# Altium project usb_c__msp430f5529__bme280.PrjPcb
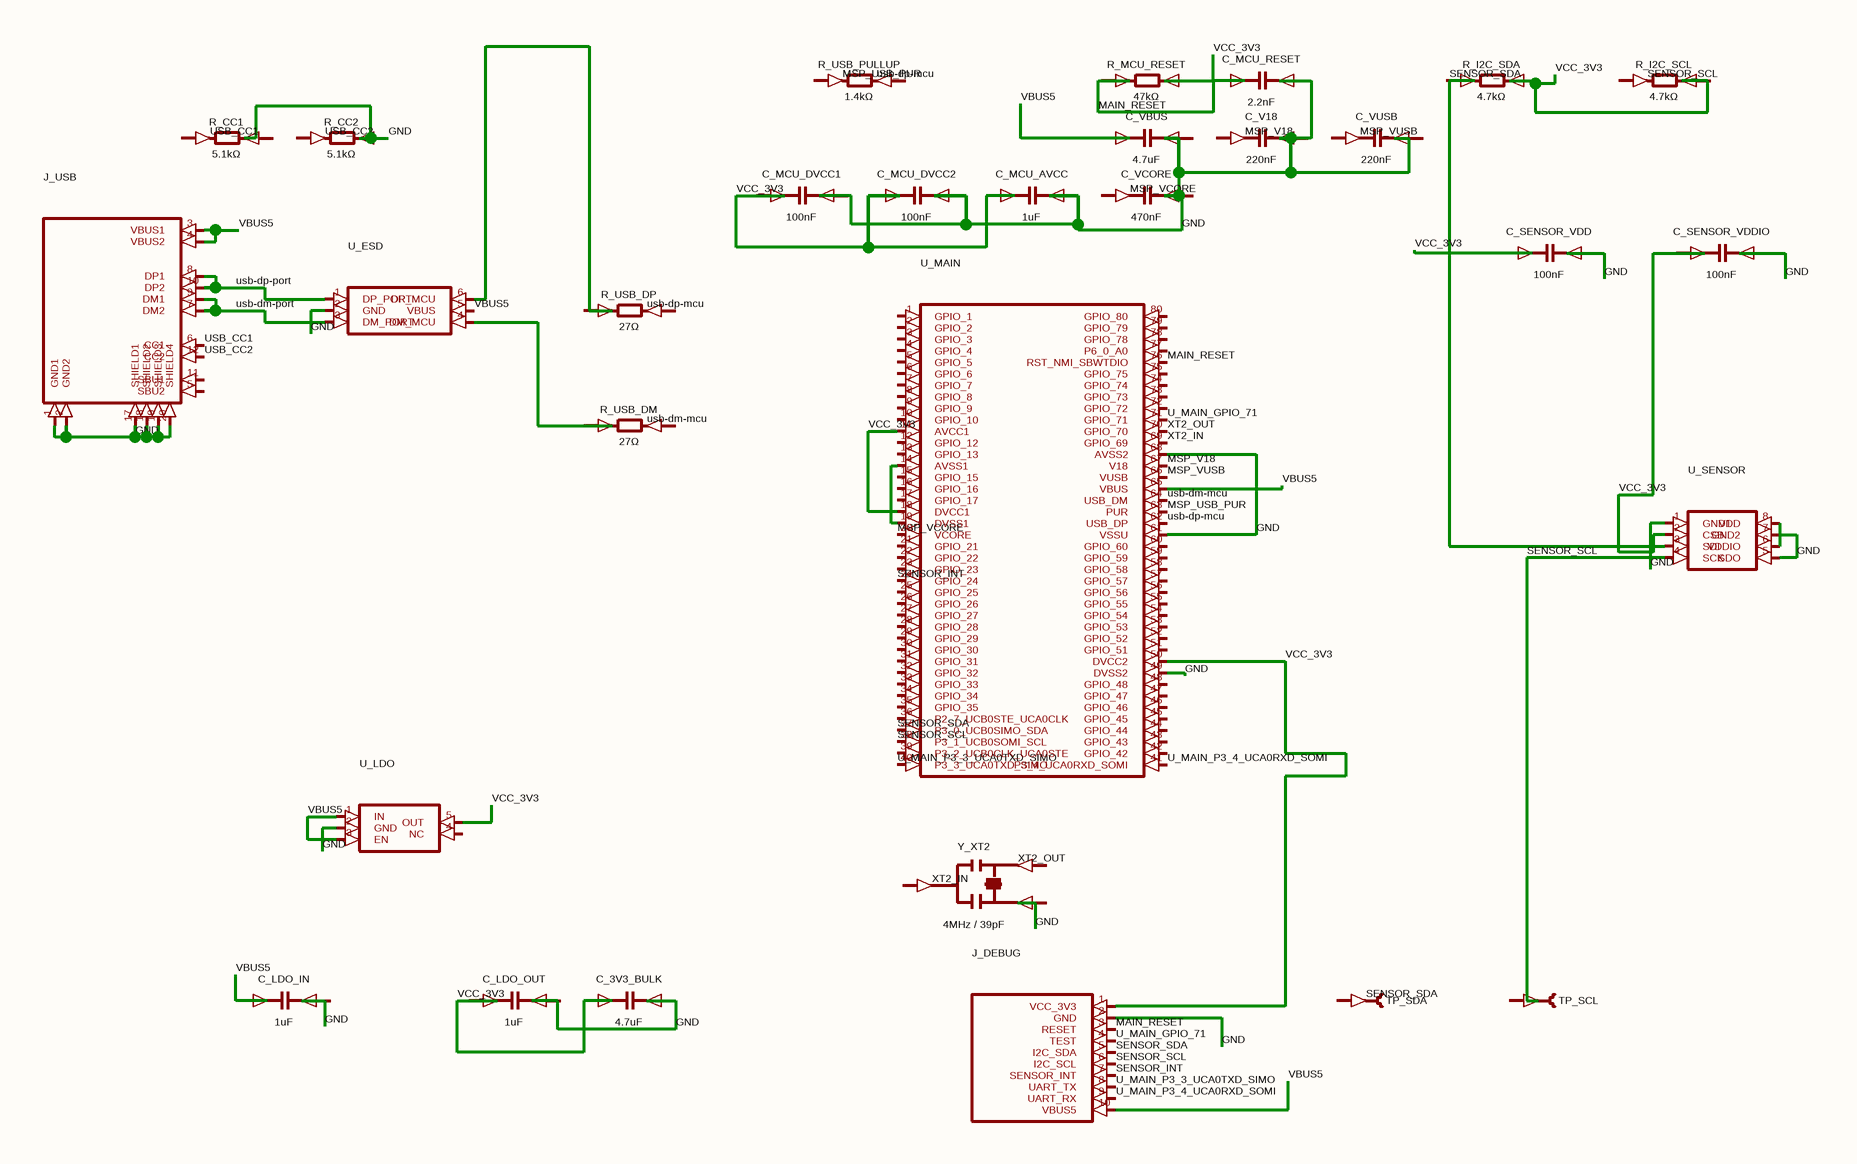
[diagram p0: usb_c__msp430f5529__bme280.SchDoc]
1 sheet, 30 parts. Net scope: global (net labels, ports and power ports of the same name join across sheets).
Board file: usb_c__msp430f5529__bme280.PcbDoc

## Sheet usb_c__msp430f5529__bme280.SchDoc
size 204 x 144 mm

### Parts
C_3V3_BULK  4.7uF
C_LDO_IN  1uF
C_LDO_OUT  1uF
C_MCU_AVCC  1uF
C_MCU_DVCC1  100nF
C_MCU_DVCC2  100nF
C_MCU_RESET  2.2nF
C_SENSOR_VDD  100nF
C_SENSOR_VDDIO  100nF
C_V18  220nF
C_VBUS  4.7uF
C_VCORE  470nF
C_VUSB  220nF
J_DEBUG  (no value)
J_USB  (no value)
R_CC1  5.1kΩ
R_CC2  5.1kΩ
R_I2C_SCL  4.7kΩ
R_I2C_SDA  4.7kΩ
R_MCU_RESET  47kΩ
R_USB_DM  27Ω
R_USB_DP  27Ω
R_USB_PULLUP  1.4kΩ
TP_SCL  (no value)
TP_SDA  (no value)
U_ESD  (no value)
U_LDO  (no value)
U_MAIN  (no value)
U_SENSOR  (no value)
Y_XT2  4MHz / 39pF

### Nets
GND: C_3V3_BULK.2(neg) C_MCU_AVCC.2(neg) C_MCU_DVCC1.2(neg) C_MCU_DVCC2.2(neg) C_MCU_RESET.2(neg) C_SENSOR_VDD.2(neg) C_SENSOR_VDDIO.2(neg) C_V18.2(neg) J_DEBUG.2(GND) J_USB.1(GND1) J_USB.2(GND2) J_USB.17(SHIELD1) J_USB.18(SHIELD2) J_USB.19(SHIELD3) J_USB.20(SHIELD4) R_CC2.2(cathode) U_ESD.2(GND) U_LDO.2(GND) U_MAIN.49(DVSS2) U_MAIN.61(VSSU) U_MAIN.68(AVSS2) U_SENSOR.1(GND1) U_SENSOR.5(SDO) U_SENSOR.6(VDDIO) U_SENSOR.7(GND2) U_SENSOR.8(VDD)
MAIN_RESET: C_3V3_BULK.1(pos) C_LDO_OUT.1(pos) C_MCU_AVCC.1(pos) C_MCU_DVCC1.1(pos) C_MCU_DVCC2.1(pos) C_MCU_RESET.1(pos) C_SENSOR_VDD.1(pos) C_SENSOR_VDDIO.1(pos) J_DEBUG.1(VCC_3V3) J_DEBUG.3(RESET) J_DEBUG.5(I2C_SDA) R_MCU_RESET.1(anode) R_MCU_RESET.2(cathode) U_LDO.5(OUT) U_MAIN.11(AVCC1) U_MAIN.18(DVCC1) U_MAIN.37(P3_0_UCB0SIMO_SDA) U_MAIN.50(DVCC2) U_MAIN.76(RST_NMI_SBWTDIO) U_SENSOR.2(CSB) U_SENSOR.3(SDI)  [also labelled SENSOR_SDA, VCC_3V3]
MSP_USB_PUR: U_MAIN.63(PUR)
MSP_V18: U_MAIN.67(V18)
MSP_VCORE: U_MAIN.20(VCORE)
MSP_VUSB: U_MAIN.66(VUSB)
SENSOR_INT: J_DEBUG.7(SENSOR_INT) U_MAIN.24(GPIO_24)
SENSOR_SCL: J_DEBUG.6(I2C_SCL) U_MAIN.38(P3_1_UCB0SOMI_SCL) U_SENSOR.4(SCK)
U_MAIN_GPIO_71: J_DEBUG.4(TEST) U_MAIN.71(GPIO_71)
U_MAIN_P3_3_UCA0TXD_SIMO: J_DEBUG.8(UART_TX) U_MAIN.40(P3_3_UCA0TXD_SIMO)
U_MAIN_P3_4_UCA0RXD_SOMI: J_DEBUG.9(UART_RX) U_MAIN.41(P3_4_UCA0RXD_SOMI)
usb-dm-mcu: U_MAIN.64(USB_DM)
usb-dm-port: J_USB.7(DM2) J_USB.9(DM1) U_ESD.3(DM_PORT)
usb-dp-mcu: U_MAIN.62(USB_DP)
usb-dp-port: J_USB.8(DP1) J_USB.10(DP2) U_ESD.1(DP_PORT)
USB_CC1: J_USB.6(CC1)
USB_CC2: J_USB.12(CC2)
VBUS5: C_LDO_IN.1(pos) C_VBUS.1(pos) J_DEBUG.10(VBUS5) J_USB.3(VBUS1) J_USB.4(VBUS2) U_ESD.5(VBUS) U_LDO.1(IN) U_LDO.3(EN) U_MAIN.65(VBUS)
XT2_IN: U_MAIN.69(GPIO_69)
XT2_OUT: U_MAIN.70(GPIO_70)
NetR_USB_DM_1: R_USB_DM.1(anode) U_ESD.4(DM_MCU)
NetU_MAIN_14: U_MAIN.14(AVSS1) U_MAIN.19(DVSS1)

Not connected (* = marked no-connect by the designer): C_LDO_IN 2(neg); C_LDO_OUT 2(neg); C_V18 1(pos); C_VBUS 2(neg); C_VCORE 1(pos) 2(neg); C_VUSB 1(pos) 2(neg); J_USB 5(SBU2) 11(SBU1); R_CC1 1(anode) 2(cathode); R_CC2 1(anode); R_I2C_SCL 1(anode) 2(cathode); R_I2C_SDA 1(anode) 2(cathode); R_USB_DM 2(cathode); R_USB_DP 1(anode) 2(cathode); R_USB_PULLUP 1(anode) 2(cathode); TP_SCL 1(pin1); TP_SDA 1(pin1); U_ESD 6(DP_MCU); U_LDO 4(NC); U_MAIN 1(GPIO_1) 2(GPIO_2) 3(GPIO_3) 4(GPIO_4) 5(GPIO_5) 6(GPIO_6) 7(GPIO_7) 8(GPIO_8) 9(GPIO_9) 10(GPIO_10) 12(GPIO_12) 13(GPIO_13) 15(GPIO_15) 16(GPIO_16) 17(GPIO_17) 21(GPIO_21) 22(GPIO_22) 23(GPIO_23) 25(GPIO_25) 26(GPIO_26) 27(GPIO_27) 28(GPIO_28) 29(GPIO_29) 30(GPIO_30) 31(GPIO_31) 32(GPIO_32) 33(GPIO_33) 34(GPIO_34) 35(GPIO_35) 36(P2_7_UCB0STE_UCA0CLK) 39(P3_2_UCB0CLK_UCA0STE) 42(GPIO_42) 43(GPIO_43) 44(GPIO_44) 45(GPIO_45) 46(GPIO_46) 47(GPIO_47) 48(GPIO_48) 51(GPIO_51) 52(GPIO_52) 53(GPIO_53) 54(GPIO_54) 55(GPIO_55) 56(GPIO_56) 57(GPIO_57) 58(GPIO_58) 59(GPIO_59) 60(GPIO_60) 72(GPIO_72) 73(GPIO_73) 74(GPIO_74) 75(GPIO_75) 77(P6_0_A0) 78(GPIO_78) 79(GPIO_79) 80(GPIO_80); Y_XT2 1(pin1) 2(pin2) 3(pin3)

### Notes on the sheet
- Labels drawn without touching a wire or pin: MSP_USB_PUR, MSP_V18, MSP_VCORE, MSP_VUSB, SENSOR_SCL, SENSOR_SDA, usb-dm-mcu, usb-dp-mcu, USB_CC1, USB_CC2, XT2_IN, XT2_OUT

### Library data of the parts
C_3V3_BULK C_LDO_IN C_LDO_OUT C_MCU_AVCC C_MCU_DVCC1 C_MCU_DVCC2 C_MCU_RESET C_SENSOR_VDD C_SENSOR_VDDIO C_V18 C_VBUS C_VCORE C_VUSB = capacitor_right
J_DEBUG = J_DEBUG
J_USB = J_USB
R_CC1 R_CC2 R_I2C_SCL R_I2C_SDA R_MCU_RESET R_USB_DM R_USB_DP R_USB_PULLUP = boxresistor_right
TP_SCL TP_SDA = testpoint_right
U_ESD = U_ESD
U_LDO = U_LDO
U_MAIN = U_MAIN
U_SENSOR = U_SENSOR
Y_XT2 = resonator_right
